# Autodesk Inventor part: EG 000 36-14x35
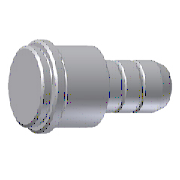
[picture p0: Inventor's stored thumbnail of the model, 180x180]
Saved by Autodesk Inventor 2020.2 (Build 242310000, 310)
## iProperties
Manager: www.cadconsulting.pl
Company: Fabian Stasiak CAD Consulting
Created: 2014-02
Part Number: EG 000 36-14x35
Material: DIN 1.7131
Description: Leader Pins
Document SubType Name: Modeling
Designer: F.Stasiak
Standard Revision: 1
Manufacturer: DME
Language: pl-PL
Size Designation: 36-14x35
Categories: <MemberInstance><Categories><Category DisplayName="Forma wtryskowa" InternalName="349578f2-f4d4-4954-8c09-8e99297a61c0" Mnemonic="MOLD"><Category DisplayName="K
Mass: 4.19143 g
Surface Area: 17.8137 cm^2
Volume: 4.19143 cm^3
Density: 7.85 g/cm^3
Appearance: Stal
Catalog Web Link: www.expertbooks.pl
IsCustomPart: 0
Author: F.Stasiak
Subject: Zbiór ćwiczeń. Autodesk Inventor 2020. Kurs Professional
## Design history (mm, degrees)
sketch "Sketch1"
  geometry: L1 (0, -42.393)-(0, 14.066) reference; L2 (0, 15)-(10, 15); L3 (10, 15)-(10, 7); L4 (9.5, 6)-(12.5, 6); L5 (12.5, 6)-(12.5, 0); L6 (12.5, 0)-(9.5, 0); L7 (10, -1)-(10, -28); L8 (10, -28)-(10, -28); L9 (10, -28)-(10, -30); L10 (10, -30)-(7, -30); L11 (7, -61)-(6.325, -63.518); L12 (4.394, -65)-(0, -65); L13 (7, -30)-(7, -61); L14 (9.5, 0)-(9.5, -1); L15 (9.5, -1)-(10, -1); L16 (9.5, 7)-(10, 7); L17 (9.5, 7)-(9.5, 6); L18 (0, 15)-(0, -65); A1 r 2 centre (4.394, -63) between (4.394, -65) and (6.325, -63.518); 1 further point
  constraints: 38 end point, 7 perpendicular, 6 parallel, 2 collinear, 2 point on circle, 2 point on line, 2 tangent, 2 vertical alignment, 1 centre point, 1 horizontal alignment
  dimensions: "d73" = 6 distance between parallel lines of L6 L4 (derived); "d74" = 9 distance between parallel lines of L2 L4 (derived); "d75" = 36 distance between parallel lines of L10 L4 (derived); "d76" = 2 distance between parallel lines of L10 L8; "d77" = 25 diameter of L5 L1 (derived); "d78" = 35 distance between parallel lines of L12 L10 (derived); "d79" = 20 diameter of L3 L1 (derived); "d89" = 4 distance from line of L12 L11.start (derived); "d92" = 14 diameter of L13 L1 (derived); "d94" = 20 diameter of L7 L1 (derived); "d97" = 2 radius of A1; "d110" = 0.5 distance between parallel lines of L7 L14; "d111" = 1 distance from line of L6.end L15; "d112" = 0.5 distance between parallel lines of L3 L17; "d113" = 1 distance between parallel lines of L4 L16; "d114" = 20 diameter of L9 L18 (derived); "d120" = 15 deg angle of L13 L11
revolve "Revolution1" sketch "Sketch1" stored, may be unused: angle "d100" = 90 deg
chamfer "Chamfer1" distance "d106" = 0.5; stored, may be unused: second distance "d107" = 2, angle "d108" = 45 deg
fillet "Fillet1" dims "d109" = 0.3
sketch "Sketch2"
  geometry: L1 (-4.394, -65)-(4.394, -65) reference; L2 (0, -40.8)-(0, 6.8) reference; C1 r 0.875 at (7.175, -40.333); C2 r 0.875 at (7.175, -50.667); 1 further point
  constraints: 2 centre point, 1 equal radius, 1 vertical alignment
  dimensions: "d121" = 1.75 diameter of C1 (derived); "d122" = 14.33333 distance from line of L1 C2.centre (derived); "d123" = 24.66667 distance from line of L1 C1.centre (derived); "d129" = 14.35 diameter of C1.centre L2 (derived)
revolve "Revolution2" sketch "Sketch2" stored, may be unused: angle "d126" = 90 deg
body "Solid1"
other parameters: "d3" = 25 [user parameter], "l2" = 9 [user parameter], "l1" = 6 [user parameter], "A_" = 36 [user parameter], "B" = 35 [user parameter], "d1" = 14 [user parameter; used in 1 equation term], "d43" = 14 (= d1), "d91" = 8, "d101" = 0, "d103" = 0, "ob" = 4 [user parameter], "B1" = 14.33333 [user parameter], "G1" = 24.66667 [user parameter], "d128" = 0, "L_" = 71 [user parameter]
